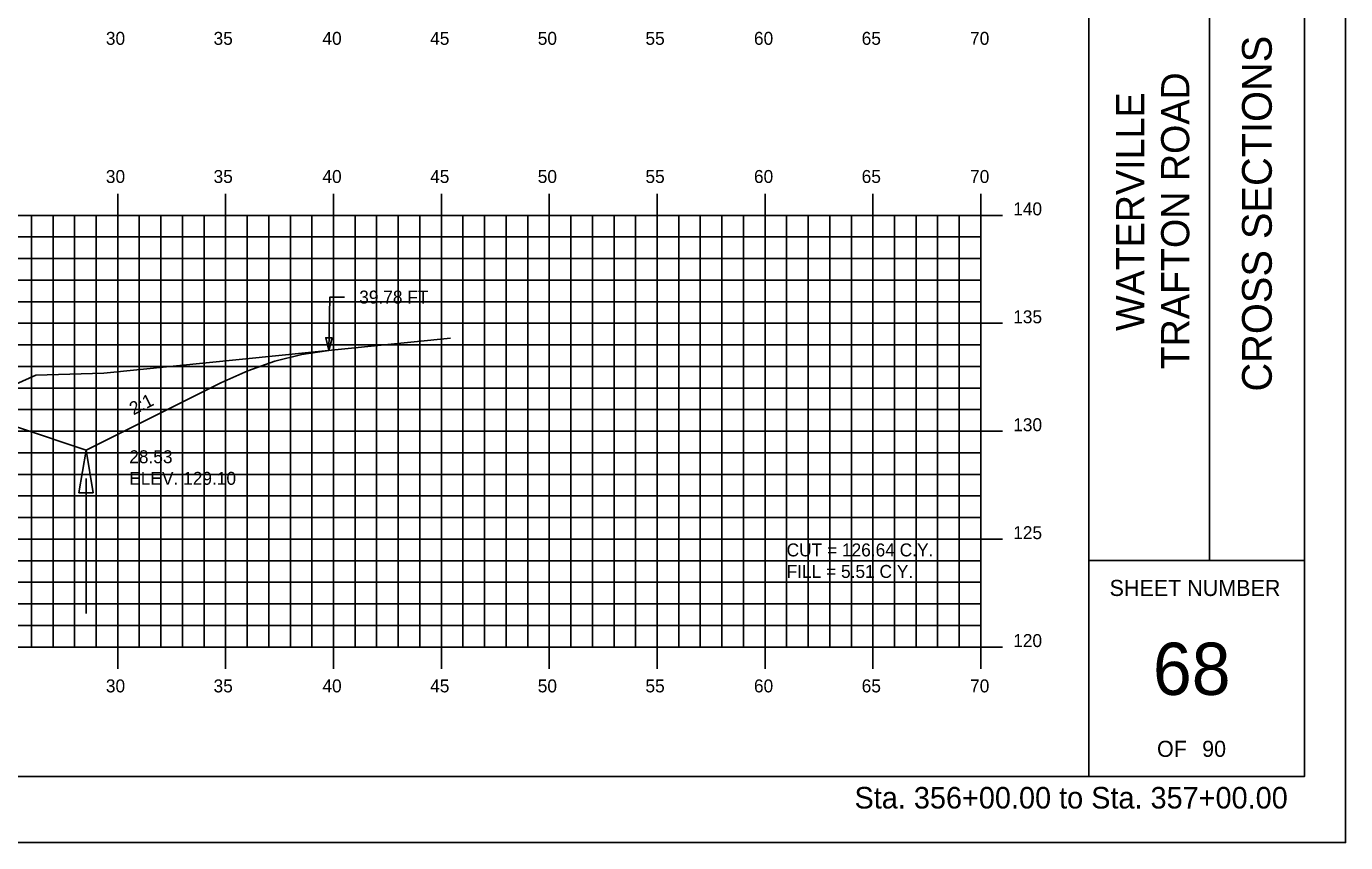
# Model space of a CAD drawing. Extents: x 1145638 to 1145808, y 608981 to 609091.
# Drawn here: x 1145746.4 to 1145807.6, y 608981.3 to 609019.1 of the extents above; entities that cross this region are included whole.
import ezdxf

# ---------------------------------------------------------------- set-up
doc = ezdxf.new("R2010")
doc.units = 0
for name, color, linetype in [('ANNOTATION', 7, 'Continuous'), ('BORDER', 7, 'Continuous'), ('D_Drainage_Ditch_Line', 7, 'Continuous'), ('D_Roadway_SlopeLines', 7, 'Continuous'), ('D_Text_Standard', 7, 'Continuous'), ('H_V ANNOTATION', 7, 'Continuous'), ('HIGHWAY_TITLE', 7, 'Continuous'), ('MAJOR', 7, 'Continuous'), ('MINOR', 7, 'Continuous'), ('PLOT BOUNDARY', 7, 'Continuous'), ('S_Roadway_Centerline', 7, 'Continuous')]:
    doc.layers.add(name, color=color, linetype=linetype)

msp = doc.modelspace()

# ---------------------------------------------------------------- linework, layer by layer
msp.add_lwpolyline([(1145683.903, 609003.924), (1145685.153, 609003.777), (1145686.403, 609003.494), (1145687.653, 609003.074), (1145688.903, 609002.517), (1145694.92, 608999.509), (1145697.92, 609000.509), (1145705.644, 609003.083), (1145705.645, 609003.083), (1145709.645, 609003.243), (1145720.645, 609003.463), (1145731.645, 609003.243), (1145738.645, 609002.963), (1145746.177, 609000.453), (1145749.177, 608999.453), (1145755.422, 609002.575), (1145756.672, 609003.138), (1145757.922, 609003.576), (1145759.172, 609003.888), (1145760.422, 609004.076)])
at = {"layer": 'BORDER'}
for p, q in [((1145795.645, 608984.335), (1145795.645, 609089.335)), ((1145801.236, 608994.338), (1145801.236, 609029.338)), ((1145795.645, 608994.338), (1145805.645, 608994.338))]:
    msp.add_line(p, q, dxfattribs=at)
msp.add_lwpolyline([(1145645.645, 608984.335), (1145805.645, 608984.335), (1145805.645, 609089.335), (1145645.645, 609089.335)], close=True, dxfattribs=at)
at = {"layer": 'D_Drainage_Ditch_Line'}
msp.add_line((1145749.177, 608998.14), (1145749.177, 608991.897), dxfattribs=at)
msp.add_lwpolyline([(1145749.505, 608997.484), (1145748.849, 608997.484), (1145749.177, 608999.453)], close=True, dxfattribs=at)
at = {"layer": 'D_Roadway_SlopeLines'}
for points in [[(1145749.177, 608999.453), (1145755.422, 609002.575), (1145756.672, 609003.138), (1145757.922, 609003.576), (1145759.172, 609003.888), (1145760.422, 609004.076)], [(1145746.177, 609000.453), (1145749.177, 608999.453)]]:
    msp.add_lwpolyline(points, dxfattribs=at)
at = {"layer": 'D_Text_Standard'}
msp.add_lwpolyline([(1145760.422, 609004.076), (1145760.475, 609006.549), (1145761.155, 609006.549)], dxfattribs=at)
msp.add_lwpolyline([(1145760.422, 609004.076), (1145760.289, 609004.661), (1145760.58, 609004.655)], close=True, dxfattribs=at)
at = {"layer": 'MAJOR'}
for p, q in [((1145750.645, 609011.337), (1145750.645, 609010.335)), ((1145755.645, 609011.337), (1145755.645, 609010.335)), ((1145760.645, 609011.337), (1145760.645, 609010.335)), ((1145765.645, 609011.337), (1145765.645, 609010.335)), ((1145770.645, 609011.337), (1145770.645, 609010.335)), ((1145775.645, 609011.337), (1145775.645, 609010.335)), ((1145780.645, 609011.337), (1145780.645, 609010.335)), ((1145785.645, 609011.337), (1145785.645, 609010.335)), ((1145790.645, 609011.337), (1145790.645, 609010.335)), ((1145650.645, 609010.335), (1145790.645, 609010.335)), ((1145650.645, 609010.335), (1145790.645, 609010.335)), ((1145750.645, 608990.335), (1145750.645, 609010.335)), ((1145755.645, 608990.335), (1145755.645, 609010.335)), ((1145760.645, 608990.335), (1145760.645, 609010.335)), ((1145765.645, 608990.335), (1145765.645, 609010.335)), ((1145770.645, 608990.335), (1145770.645, 609010.335)), ((1145775.645, 608990.335), (1145775.645, 609010.335)), ((1145780.645, 608990.335), (1145780.645, 609010.335)), ((1145785.645, 608990.335), (1145785.645, 609010.335)), ((1145791.647, 609010.335), (1145789.643, 609010.335)), ((1145790.645, 608990.335), (1145790.645, 609010.335)), ((1145790.645, 608990.335), (1145790.645, 609010.335)), ((1145650.645, 609005.335), (1145790.645, 609005.335)), ((1145791.647, 609005.335), (1145789.643, 609005.335)), ((1145650.645, 609000.335), (1145790.645, 609000.335)), ((1145791.647, 609000.335), (1145789.643, 609000.335)), ((1145650.645, 608995.335), (1145790.645, 608995.335)), ((1145791.647, 608995.335), (1145789.643, 608995.335)), ((1145650.645, 608990.335), (1145790.645, 608990.335)), ((1145650.645, 608990.335), (1145790.645, 608990.335)), ((1145750.645, 608989.333), (1145750.645, 608990.335)), ((1145755.645, 608989.333), (1145755.645, 608990.335)), ((1145760.645, 608989.333), (1145760.645, 608990.335)), ((1145765.645, 608989.333), (1145765.645, 608990.335)), ((1145770.645, 608989.333), (1145770.645, 608990.335)), ((1145775.645, 608989.333), (1145775.645, 608990.335)), ((1145780.645, 608989.333), (1145780.645, 608990.335)), ((1145785.645, 608989.333), (1145785.645, 608990.335)), ((1145791.647, 608990.335), (1145789.643, 608990.335)), ((1145790.645, 608989.333), (1145790.645, 608990.335))]:
    msp.add_line(p, q, dxfattribs=at)
at = {"layer": 'MINOR'}
for p, q in [((1145746.645, 608990.335), (1145746.645, 609010.335)), ((1145747.645, 608990.335), (1145747.645, 609010.335)), ((1145748.645, 608990.335), (1145748.645, 609010.335)), ((1145749.645, 608990.335), (1145749.645, 609010.335)), ((1145751.645, 608990.335), (1145751.645, 609010.335)), ((1145752.645, 608990.335), (1145752.645, 609010.335)), ((1145753.645, 608990.335), (1145753.645, 609010.335)), ((1145754.645, 608990.335), (1145754.645, 609010.335)), ((1145756.645, 608990.335), (1145756.645, 609010.335)), ((1145757.645, 608990.335), (1145757.645, 609010.335)), ((1145758.645, 608990.335), (1145758.645, 609010.335)), ((1145759.645, 608990.335), (1145759.645, 609010.335)), ((1145761.645, 608990.335), (1145761.645, 609010.335)), ((1145762.645, 608990.335), (1145762.645, 609010.335)), ((1145763.645, 608990.335), (1145763.645, 609010.335)), ((1145764.645, 608990.335), (1145764.645, 609010.335)), ((1145766.645, 608990.335), (1145766.645, 609010.335)), ((1145767.645, 608990.335), (1145767.645, 609010.335)), ((1145768.645, 608990.335), (1145768.645, 609010.335)), ((1145769.645, 608990.335), (1145769.645, 609010.335)), ((1145771.645, 608990.335), (1145771.645, 609010.335)), ((1145772.645, 608990.335), (1145772.645, 609010.335)), ((1145773.645, 608990.335), (1145773.645, 609010.335)), ((1145774.645, 608990.335), (1145774.645, 609010.335)), ((1145776.645, 608990.335), (1145776.645, 609010.335)), ((1145777.645, 608990.335), (1145777.645, 609010.335)), ((1145778.645, 608990.335), (1145778.645, 609010.335)), ((1145779.645, 608990.335), (1145779.645, 609010.335)), ((1145781.645, 608990.335), (1145781.645, 609010.335)), ((1145782.645, 608990.335), (1145782.645, 609010.335)), ((1145783.645, 608990.335), (1145783.645, 609010.335)), ((1145784.645, 608990.335), (1145784.645, 609010.335)), ((1145786.645, 608990.335), (1145786.645, 609010.335)), ((1145787.645, 608990.335), (1145787.645, 609010.335)), ((1145788.645, 608990.335), (1145788.645, 609010.335)), ((1145789.645, 608990.335), (1145789.645, 609010.335)), ((1145650.645, 609009.335), (1145790.645, 609009.335)), ((1145790.645, 609009.335), (1145789.643, 609009.335)), ((1145650.645, 609008.335), (1145790.645, 609008.335)), ((1145790.645, 609008.335), (1145789.643, 609008.335)), ((1145650.645, 609007.335), (1145790.645, 609007.335)), ((1145790.645, 609007.335), (1145789.643, 609007.335)), ((1145650.645, 609006.335), (1145790.645, 609006.335)), ((1145790.645, 609006.335), (1145789.643, 609006.335)), ((1145650.645, 609004.335), (1145790.645, 609004.335)), ((1145790.645, 609004.335), (1145789.643, 609004.335)), ((1145650.645, 609003.335), (1145790.645, 609003.335)), ((1145790.645, 609003.335), (1145789.643, 609003.335)), ((1145650.645, 609002.335), (1145790.645, 609002.335)), ((1145790.645, 609002.335), (1145789.643, 609002.335)), ((1145650.645, 609001.335), (1145790.645, 609001.335)), ((1145790.645, 609001.335), (1145789.643, 609001.335)), ((1145650.645, 608999.335), (1145790.645, 608999.335)), ((1145790.645, 608999.335), (1145789.643, 608999.335)), ((1145650.645, 608998.335), (1145790.645, 608998.335)), ((1145790.645, 608998.335), (1145789.643, 608998.335)), ((1145650.645, 608997.335), (1145790.645, 608997.335)), ((1145790.645, 608997.335), (1145789.643, 608997.335)), ((1145650.645, 608996.335), (1145790.645, 608996.335)), ((1145790.645, 608996.335), (1145789.643, 608996.335)), ((1145650.645, 608994.335), (1145790.645, 608994.335)), ((1145790.645, 608994.335), (1145789.643, 608994.335)), ((1145650.645, 608993.335), (1145790.645, 608993.335)), ((1145790.645, 608993.335), (1145789.643, 608993.335)), ((1145650.645, 608992.335), (1145790.645, 608992.335)), ((1145790.645, 608992.335), (1145789.643, 608992.335)), ((1145650.645, 608991.335), (1145790.645, 608991.335)), ((1145790.645, 608991.335), (1145789.643, 608991.335))]:
    msp.add_line(p, q, dxfattribs=at)
at = {"layer": 'PLOT BOUNDARY'}
msp.add_lwpolyline([(1145637.552, 608981.276), (1145807.552, 608981.276), (1145807.552, 609091.276), (1145637.552, 609091.276)], close=True, dxfattribs=at)
at = {"layer": 'S_Roadway_Centerline'}
msp.add_lwpolyline([(1145665.284, 609004.253), (1145674.048, 609004.329), (1145676.611, 609004.338), (1145686.027, 609003.803), (1145691.493, 609003.283), (1145697.515, 609000.943), (1145701.06, 608999.985), (1145703.047, 609000.3), (1145704.751, 609000.59), (1145706.442, 609000.759), (1145707.087, 609000.832), (1145707.467, 609000.81), (1145715.52, 609001.007), (1145718.557, 609001.09), (1145727.194, 609000.779), (1145729.795, 609000.725), (1145730.727, 609000.642), (1145734.227, 609000.27), (1145736.145, 608999.62), (1145736.754, 608999.333), (1145745.298, 609002.239), (1145746.848, 609002.934), (1145749.998, 609003.03), (1145766.074, 609004.643)], dxfattribs=at)

# ---------------------------------------------------------------- texts
at = {"layer": 'ANNOTATION'}
msp.add_text('2:1', height=0.6, rotation=26.56505, dxfattribs=at).set_placement((1145751.372, 609001.068))
at = {"layer": 'BORDER'}
msp.add_text('CROSS SECTIONS', height=1.37787, rotation=90, dxfattribs=at).set_placement((1145804.13, 609002.172))
for s, height, p in [('SHEET NUMBER', 0.74527, (1145796.611, 608992.701)), ('68', 2.4194, (1145798.621, 608988.118)), ('OF', 0.7453, (1145798.812, 608985.248)), ('90', 0.7453, (1145800.902, 608985.248))]:
    msp.add_text(s, height=height, dxfattribs=at).set_placement(p)
at = {"layer": 'D_Text_Standard'}
for s, p in [('39.78 FT', (1145761.835, 609006.249)), ('28.53', (1145751.177, 608998.853)), ('ELEV. 129.10', (1145751.177, 608997.851)), ('CUT = 126.64 C.Y.', (1145781.645, 608994.535)), ('FILL = 5.51 C.Y.', (1145781.645, 608993.539))]:
    msp.add_text(s, height=0.6, dxfattribs=at).set_placement(p)
at = {"layer": 'H_V ANNOTATION'}
for s, height, p in [('30', 0.6, (1145750.094, 609018.235)), ('35', 0.6, (1145755.086, 609018.235)), ('40', 0.6, (1145760.131, 609018.235)), ('45', 0.6, (1145765.123, 609018.235)), ('50', 0.6, (1145770.11, 609018.235)), ('55', 0.6, (1145775.102, 609018.235)), ('60', 0.6, (1145780.131, 609018.235)), ('65', 0.6, (1145785.123, 609018.235)), ('70', 0.6, (1145790.147, 609018.235)), ('30', 0.6, (1145750.094, 609011.835)), ('35', 0.6, (1145755.086, 609011.835)), ('40', 0.6, (1145760.131, 609011.835)), ('45', 0.6, (1145765.123, 609011.835)), ('50', 0.6, (1145770.11, 609011.835)), ('55', 0.6, (1145775.102, 609011.835)), ('60', 0.6, (1145780.131, 609011.835)), ('65', 0.6, (1145785.123, 609011.835)), ('70', 0.6, (1145790.147, 609011.835)), ('140', 0.6, (1145792.145, 609010.335)), ('135', 0.6, (1145792.145, 609005.335)), ('130', 0.6, (1145792.145, 609000.335)), ('125', 0.6, (1145792.145, 608995.335)), ('120', 0.6, (1145792.145, 608990.335)), ('30', 0.6, (1145750.094, 608988.235)), ('35', 0.6, (1145755.086, 608988.235)), ('40', 0.6, (1145760.131, 608988.235)), ('45', 0.6, (1145765.123, 608988.235)), ('50', 0.6, (1145770.11, 608988.235)), ('55', 0.6, (1145775.102, 608988.235)), ('60', 0.6, (1145780.131, 608988.235)), ('65', 0.6, (1145785.123, 608988.235)), ('70', 0.6, (1145790.147, 608988.235)), ('Sta. 356+00.00 to Sta. 357+00.00', 1.0002, (1145784.791, 608982.855))]:
    msp.add_text(s, height=height, dxfattribs=at).set_placement(p)
at = {"layer": 'HIGHWAY_TITLE'}
for s, height, p in [('TRAFTON ROAD', 1.30428, (1145800.305, 609003.201)), ('WATERVILLE', 1.3043, (1145798.218, 609004.98))]:
    msp.add_text(s, height=height, rotation=90, dxfattribs=at).set_placement(p)

doc.saveas('drawing.dxf')
